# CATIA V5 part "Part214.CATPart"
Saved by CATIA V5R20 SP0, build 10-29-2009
Part number: FA 168700-1
Revision: ANY
Definition: UNKNOWN
Nomenclature: FA 168700-1
Source: Unknown
Bounding box of the stored display mesh (mm): x -3.804 to 3.804, y 0.28 to 2.5, z -4 to 4
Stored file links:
  C:\Users\Utente\Desktop\IO LAVORO\3D X SITO CF\CUMSA\3D files FA\FA 200710-20\Part214.CATPart

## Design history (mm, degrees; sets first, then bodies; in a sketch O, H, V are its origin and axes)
Body1 "Cortar-Extruir1" (main body)
  Solid1: solid without history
